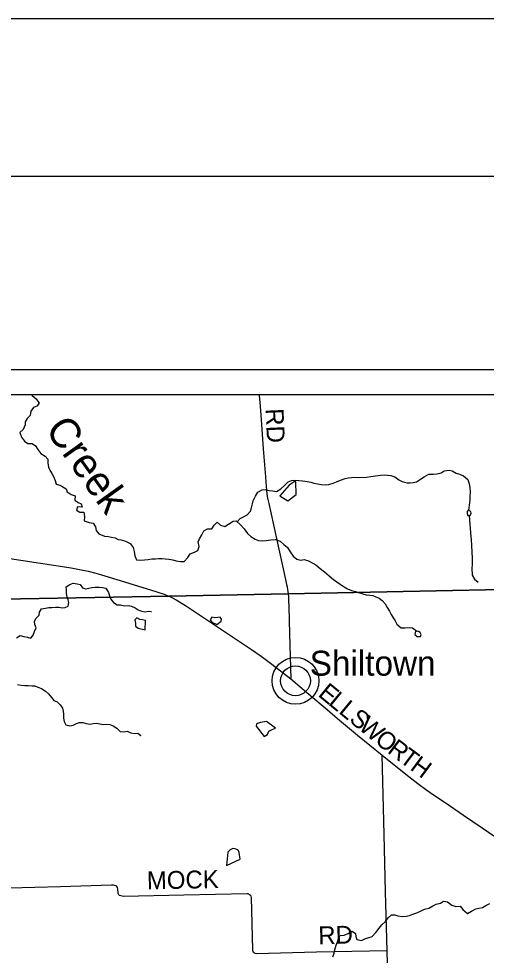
# Model space of a CAD drawing. Extents: x 0 to 34, y 0 to 22.
# Drawn here: x 5.224 to 6.707, y 19.028 to 22 of the extents above; entities that cross this region are included whole.
import ezdxf

# ---------------------------------------------------------------- set-up
doc = ezdxf.new("R2010")
doc.units = 0
for name, color, linetype in [('GM_X_Corporation', 7, 'Continuous'), ('GM_X_County_Road', 7, 'Continuous'), ('GM_X_County_Road_Text', 7, 'Continuous'), ('GM_X_Minor_Lake', 7, 'Continuous'), ('GM_X_Minor_River', 7, 'Continuous'), ('GM_X_Minor_River_Text', 7, 'Continuous'), ('GM_X_Township_Road', 7, 'Continuous'), ('GM_X_Unincorporated', 7, 'Continuous'), ('GM_X_Unincorporated_Location', 7, 'Continuous'), ('GM_X_Unincorporated_Text', 7, 'Continuous'), ('SH_Border', 7, 'Continuous'), ('SH_Cut_Line', 7, 'Continuous'), ('SH_Data', 7, 'Continuous')]:
    doc.layers.add(name, color=color, linetype=linetype)

msp = doc.modelspace()

# ---------------------------------------------------------------- linework, layer by layer
at = {"layer": 'GM_X_Corporation'}
msp.add_lwpolyline([(7.2136, 20.8069), (2.9895, 20.8069), (2.9895, 20.1176), (3.1549, 20.1187), (4.9925, 20.1548), (5.7004, 20.168), (6.0786, 20.1754), (7.2254, 20.198), (7.2157, 20.6753), (7.2146, 20.7526)], close=True, dxfattribs=at)
msp.add_lwpolyline([(7.2872, 17.1772), (7.283, 17.3071), (7.2799, 17.4174), (7.2764, 17.5202), (7.2751, 17.5764), (7.2467, 19.0557), (7.2468, 19.0896), (7.2426, 19.2998), (7.2392, 19.4543), (7.237, 19.6097), (7.2344, 19.7492), (7.2317, 19.8848), (7.2291, 20.0061), (7.2266, 20.122), (7.2254, 20.198), (6.0786, 20.1754), (5.7004, 20.168), (4.9925, 20.1548), (3.1549, 20.1187), (2.9895, 20.1176), (2.9895, 14.989)], dxfattribs=at)
at = {"layer": 'GM_X_County_Road'}
for points in [[(5.9866, 20.8069), (5.9868, 20.8036), (5.9886, 20.7837), (5.9932, 20.7287), (5.9994, 20.6355), (6.006, 20.5464), (6.0073, 20.5298), (6.0087, 20.5163), (6.0099, 20.504), (6.0111, 20.4923), (6.0133, 20.4791), (6.0171, 20.4614), (6.0397, 20.3598), (6.0698, 20.2206), (6.0733, 20.2043), (6.0747, 20.1975), (6.0763, 20.1891), (6.0777, 20.1824), (6.0788, 20.1749)], [(4.9883, 20.3188), (5.1818, 20.289), (5.3898, 20.2573), (5.4168, 20.2524), (5.4434, 20.2468), (5.4679, 20.2408), (5.4969, 20.2325), (5.5346, 20.2207), (5.6555, 20.1834), (5.6709, 20.1787)], [(5.6709, 20.1787), (5.6747, 20.1776), (5.6849, 20.1741), (5.694, 20.1704), (5.7006, 20.1675), (5.7093, 20.1632), (5.723, 20.156), (5.734, 20.1499), (5.7554, 20.1363), (5.838, 20.0814), (5.9084, 20.0341), (5.9617, 19.9985), (5.9928, 19.9771), (6.0264, 19.9525), (6.0866, 19.9058)], [(6.0788, 20.1749), (6.0793, 20.166), (6.0796, 20.1527), (6.0802, 20.1354), (6.0823, 20.0486), (6.0866, 19.9058)], [(6.0866, 19.9058), (6.1443, 19.8572), (6.2021, 19.8083), (6.2352, 19.7801), (6.2988, 19.727), (6.3765, 19.6635), (6.4512, 19.6033), (6.4897, 19.573), (6.5179, 19.5524), (6.5426, 19.5352), (6.5762, 19.5126), (6.6344, 19.4729), (6.6938, 19.4327), (6.7714, 19.3798), (6.8099, 19.3535), (6.8403, 19.3326), (6.8836, 19.3029), (6.9403, 19.2642), (6.994, 19.2279), (7.0243, 19.2074), (7.0735, 19.1741), (7.1379, 19.1298), (7.2009, 19.0868), (7.2469, 19.0552)], [(6.3926, 19.0426), (6.1683, 19.0378), (5.9778, 19.0332), (5.974, 19.0341), (5.9714, 19.0353), (5.9688, 19.0373), (5.9671, 19.0398), (5.9664, 19.0424), (5.9662, 19.0454), (5.9618, 19.2116), (5.9607, 19.2154), (5.9586, 19.2181), (5.9561, 19.2203), (5.9535, 19.2219), (5.951, 19.223), (5.9482, 19.2235), (5.7474, 19.219), (5.5563, 19.2152), (5.5514, 19.2155), (5.547, 19.2166), (5.5436, 19.2183), (5.5413, 19.2204), (5.54, 19.2227), (5.5391, 19.2256), (5.5375, 19.2393), (5.5367, 19.2434), (5.5343, 19.2464), (5.5312, 19.2484), (5.5279, 19.2497), (5.524, 19.2505), (5.5184, 19.2507), (5.356, 19.2459), (5.1937, 19.2412)]]:
    msp.add_lwpolyline(points, dxfattribs=at)
at = {"layer": 'GM_X_Minor_Lake'}
for points in [[(6.1037, 20.4902), (6.1027, 20.5305), (6.097, 20.5304), (6.0812, 20.5196), (6.0524, 20.4865), (6.0769, 20.4705)], [(6.0769, 20.4705), (6.1037, 20.4902)], [(6.649, 20.4411), (6.6461, 20.4364), (6.6463, 20.4296), (6.6487, 20.4236), (6.6559, 20.4238), (6.6584, 20.4307), (6.6575, 20.4352), (6.6556, 20.4374)], [(6.6556, 20.4374), (6.6541, 20.4394), (6.6514, 20.4408), (6.6498, 20.4413), (6.649, 20.4411)], [(5.6257, 20.0908), (5.6162, 20.0929), (5.6078, 20.094), (5.5979, 20.0988), (5.5923, 20.0926), (5.5935, 20.082), (5.5944, 20.0721), (5.6021, 20.0661), (5.6242, 20.0611)], [(5.6242, 20.0611), (5.6257, 20.0908)], [(5.8661, 20.088), (5.8668, 20.0945), (5.8629, 20.1009), (5.8553, 20.1001), (5.8462, 20.0992), (5.8363, 20.101), (5.8311, 20.0929), (5.8357, 20.0857), (5.8518, 20.0776)], [(5.8518, 20.0776), (5.8661, 20.088)], [(6.4827, 20.0566), (6.4807, 20.0463), (6.4881, 20.04), (6.498, 20.0399), (6.5001, 20.0464), (6.4973, 20.0528), (6.4919, 20.0557), (6.49, 20.0561)], [(6.49, 20.0561), (6.4827, 20.0566)], [(6.0092, 19.77), (5.9902, 19.7671), (5.9812, 19.7639), (5.9778, 19.7612), (5.9771, 19.7551), (6.0026, 19.7228), (6.0128, 19.729), (6.0165, 19.7397), (6.0274, 19.7447), (6.038, 19.749)], [(6.038, 19.749), (6.0092, 19.77)], [(5.9258, 19.3336), (5.9228, 19.3548), (5.9193, 19.362), (5.9155, 19.3642), (5.9101, 19.3661), (5.9032, 19.3668), (5.8942, 19.3628), (5.887, 19.3555), (5.8831, 19.3133)], [(5.8831, 19.3133), (5.9258, 19.3336)]]:
    msp.add_lwpolyline(points, dxfattribs=at)
at = {"layer": 'GM_X_Minor_River'}
for points in [[(5.2639, 20.8069), (5.2658, 20.8049), (5.279, 20.7938), (5.2888, 20.7803), (5.2811, 20.7707), (5.2709, 20.7662), (5.2625, 20.7543), (5.2597, 20.7413), (5.25, 20.7319), (5.2442, 20.7208), (5.2437, 20.7109), (5.2375, 20.697), (5.2275, 20.6869), (5.2328, 20.6726), (5.2415, 20.6595), (5.2523, 20.6525), (5.266, 20.6525), (5.2764, 20.6447), (5.2843, 20.6331), (5.2941, 20.62), (5.3076, 20.6124), (5.3155, 20.6023), (5.3154, 20.5905), (5.3183, 20.5776), (5.3227, 20.5679), (5.3287, 20.5574), (5.3339, 20.5472), (5.3387, 20.5348)], [(5.9164, 20.4037), (5.9266, 20.4147), (5.9363, 20.4199), (5.9488, 20.4255), (5.9584, 20.4379), (5.9619, 20.4478), (5.965, 20.4608), (5.9675, 20.4708), (5.9751, 20.485), (5.9824, 20.4981), (5.9956, 20.5057), (6.0054, 20.5059), (6.0184, 20.5035), (6.0291, 20.5015), (6.0417, 20.5003), (6.0556, 20.5082), (6.0664, 20.5187), (6.0787, 20.5304), (6.0892, 20.5352), (6.0991, 20.5355), (6.112, 20.535), (6.1238, 20.5337), (6.1391, 20.5318), (6.1498, 20.529), (6.1602, 20.5262), (6.1712, 20.5238), (6.1838, 20.5218), (6.1953, 20.5206), (6.2071, 20.5216), (6.2214, 20.5265), (6.2316, 20.5309), (6.244, 20.5362), (6.2587, 20.5415), (6.2689, 20.5436), (6.2792, 20.5442), (6.2913, 20.5449), (6.3016, 20.5447), (6.3271, 20.5453), (6.3411, 20.5472), (6.3555, 20.5494), (6.3714, 20.5517), (6.3832, 20.5524), (6.3939, 20.5518), (6.4038, 20.5506), (6.4164, 20.5459), (6.4292, 20.5371), (6.4396, 20.5316), (6.4545, 20.527), (6.4652, 20.5269), (6.4751, 20.5283), (6.486, 20.5308), (6.498, 20.5394), (6.5096, 20.5469), (6.5243, 20.5545), (6.5391, 20.5552), (6.5497, 20.5559), (6.5633, 20.5592), (6.5735, 20.5655), (6.5886, 20.5678), (6.5982, 20.565), (6.6113, 20.5584), (6.6216, 20.5549), (6.6347, 20.5495), (6.6479, 20.5384), (6.6524, 20.5244), (6.6546, 20.5127), (6.6557, 20.4975), (6.6549, 20.4846), (6.6543, 20.475), (6.6531, 20.4644), (6.6508, 20.441)], [(5.3387, 20.5348), (5.342, 20.5234), (5.3539, 20.5195), (5.3636, 20.5144), (5.374, 20.5086), (5.3769, 20.4988), (5.39, 20.4907), (5.403, 20.4861), (5.4018, 20.4728), (5.4123, 20.465), (5.4219, 20.4603), (5.4244, 20.4505), (5.4103, 20.4517), (5.4067, 20.4406), (5.4175, 20.4344), (5.4305, 20.4339), (5.4323, 20.4195), (5.4311, 20.4069), (5.4469, 20.4012), (5.4602, 20.3992), (5.4669, 20.388), (5.4695, 20.3763), (5.4777, 20.3654), (5.4962, 20.3586), (5.5088, 20.3567), (5.5183, 20.3554), (5.5294, 20.3533), (5.539, 20.3471), (5.5489, 20.3462), (5.5627, 20.3419), (5.5773, 20.3354), (5.5871, 20.3227), (5.5897, 20.3095), (5.5923, 20.2959), (5.5972, 20.2834), (5.6109, 20.2815), (5.6231, 20.2829), (5.6337, 20.2843), (5.6454, 20.2861), (5.6572, 20.2867), (5.6671, 20.2874), (5.6774, 20.2872), (5.688, 20.2863), (5.6999, 20.2855), (5.7128, 20.2831), (5.7228, 20.2799), (5.7373, 20.2776), (5.7484, 20.2775), (5.7602, 20.2903), (5.7679, 20.3019), (5.7811, 20.3075), (5.7916, 20.3131), (5.7959, 20.325), (5.7933, 20.3401), (5.7969, 20.3497), (5.8042, 20.3628), (5.8103, 20.3755), (5.8228, 20.3811), (5.8357, 20.3814), (5.8434, 20.3934), (5.8531, 20.4027), (5.8636, 20.3927), (5.877, 20.3892), (5.889, 20.3967), (5.904, 20.4054), (5.9134, 20.4064), (5.9274, 20.3938), (5.9391, 20.3812), (5.9494, 20.3666), (5.9595, 20.3573), (5.9738, 20.3489), (5.9841, 20.3446), (5.9971, 20.3434), (6.0089, 20.344), (6.0229, 20.3462), (6.0377, 20.3473), (6.0527, 20.3424), (6.0647, 20.3316), (6.076, 20.322), (6.085, 20.3085), (6.0937, 20.2947), (6.1057, 20.2847), (6.1184, 20.2816), (6.129, 20.2837), (6.1424, 20.2795), (6.1562, 20.2722), (6.1659, 20.2671), (6.1794, 20.256), (6.1938, 20.2453), (6.2082, 20.2323), (6.2217, 20.2209), (6.2326, 20.2128), (6.2434, 20.2058), (6.2562, 20.197), (6.2662, 20.1907), (6.2789, 20.1853), (6.2915, 20.1822), (6.3014, 20.1798), (6.3149, 20.1751), (6.3263, 20.1724), (6.337, 20.1711)], [(6.6527, 20.4237), (6.6543, 20.3948), (6.6557, 20.3823), (6.6572, 20.3702), (6.6583, 20.3565), (6.6592, 20.3467), (6.6604, 20.33), (6.6609, 20.3079), (6.6621, 20.2893), (6.6623, 20.2798), (6.6619, 20.2669), (6.6614, 20.2566), (6.6619, 20.2346), (6.6694, 20.2222), (6.6814, 20.2126)], [(5.2169, 20.0352), (5.2279, 20.0433), (5.2401, 20.0399), (5.2511, 20.0381), (5.2622, 20.0348), (5.2689, 20.0444), (5.2738, 20.0554), (5.279, 20.0672), (5.2751, 20.0775), (5.2731, 20.087), (5.278, 20.0969), (5.2881, 20.1072), (5.2896, 20.1167), (5.2959, 20.1278), (5.3081, 20.1298), (5.3191, 20.1314), (5.329, 20.1319), (5.3404, 20.1324), (5.3503, 20.1324), (5.361, 20.1306), (5.3704, 20.1322), (5.3803, 20.1361), (5.3825, 20.1472), (5.3805, 20.1566), (5.3774, 20.1661), (5.3754, 20.1767), (5.3753, 20.1878), (5.374, 20.1976), (5.3862, 20.2046), (5.3964, 20.2088), (5.4086, 20.2067), (5.4189, 20.2045)], [(5.4189, 20.2045), (5.4254, 20.1939), (5.4357, 20.1909), (5.4456, 20.1929), (5.4551, 20.1956), (5.4661, 20.1961), (5.4786, 20.1962), (5.4897, 20.1952), (5.4996, 20.1933), (5.5085, 20.1797), (5.512, 20.1687), (5.5155, 20.1581), (5.5247, 20.1472), (5.5362, 20.1408), (5.5469, 20.1401), (5.5587, 20.1376), (5.5708, 20.138), (5.5815, 20.1362), (5.5926, 20.1306), (5.6025, 20.1246), (5.6128, 20.1205), (5.6243, 20.118), (5.6345, 20.1199), (5.644, 20.1196), (5.6448, 20.1193)], [(6.337, 20.1711), (6.3469, 20.1694), (6.3569, 20.1659), (6.3669, 20.1612), (6.3766, 20.1542), (6.386, 20.1437), (6.3923, 20.1317), (6.3995, 20.1197), (6.4047, 20.1096), (6.411, 20.0991), (6.4173, 20.089), (6.4236, 20.0792), (6.4368, 20.067), (6.4494, 20.0669), (6.4631, 20.0687), (6.4726, 20.0678), (6.4866, 20.0563)], [(5.2201, 19.887), (5.2308, 19.8855), (5.2434, 19.8841), (5.2536, 19.8846), (5.2647, 19.8832), (5.2742, 19.8829), (5.2841, 19.8791), (5.2963, 19.8747), (5.3082, 19.8668), (5.3185, 19.8578), (5.3274, 19.8464), (5.3351, 19.8366), (5.345, 19.8325), (5.355, 19.8235), (5.3623, 19.8125), (5.3647, 19.8026), (5.3659, 19.7931), (5.366, 19.781), (5.3672, 19.7704), (5.3726, 19.7598), (5.3852, 19.7564), (5.3962, 19.758), (5.4065, 19.7642), (5.4159, 19.7669), (5.427, 19.7674), (5.438, 19.7633), (5.4498, 19.7619), (5.4597, 19.7639), (5.47, 19.7643), (5.4814, 19.7622), (5.4917, 19.7603), (5.5019, 19.7619), (5.513, 19.7609), (5.5233, 19.7564), (5.5348, 19.7493), (5.5459, 19.7387), (5.5569, 19.7377), (5.568, 19.7393), (5.5794, 19.7341), (5.5908, 19.7315), (5.6011, 19.7331), (5.6107, 19.7252), (5.6099, 19.7248)], [(6.2202, 19.0229), (6.2245, 19.0348), (6.2265, 19.0459), (6.2307, 19.0601), (6.2347, 19.0712), (6.2382, 19.0815), (6.2437, 19.0912), (6.2555, 19.0926), (6.2691, 19.0971), (6.281, 19.105), (6.2922, 19.0976), (6.2925, 19.0877), (6.2965, 19.0779), (6.311, 19.0756), (6.3216, 19.0808), (6.3314, 19.0841), (6.3446, 19.0878), (6.3569, 19.1003), (6.3668, 19.1142), (6.3757, 19.1247), (6.3872, 19.1359), (6.3953, 19.1468), (6.4057, 19.1565), (6.4168, 19.1564), (6.4267, 19.1536), (6.4416, 19.1517), (6.453, 19.1523), (6.4629, 19.1544), (6.4738, 19.1585), (6.487, 19.1626), (6.5006, 19.169), (6.5111, 19.1742), (6.5247, 19.1779), (6.5378, 19.1851), (6.5476, 19.1906), (6.5612, 19.1932), (6.5713, 19.1999), (6.5843, 19.198), (6.5971, 19.1868), (6.6105, 19.183), (6.6235, 19.1837), (6.6328, 19.1732), (6.6468, 19.161), (6.6603, 19.1678), (6.6739, 19.1753), (6.6837, 19.1775), (6.695, 19.1804), (6.7052, 19.1859), (6.7183, 19.1931)]]:
    msp.add_lwpolyline(points, dxfattribs=at)
at = {"layer": 'GM_X_Township_Road'}
msp.add_lwpolyline([(6.408, 18.4195), (6.4068, 18.4524), (6.4043, 18.5569), (6.3989, 18.7778), (6.3954, 18.9178), (6.3926, 19.0426), (6.3876, 19.2294), (6.383, 19.4112), (6.3765, 19.6635)], dxfattribs=at)
at = {"layer": 'GM_X_Unincorporated'}
for radius in [0.0744, 0.0472]:
    msp.add_circle((6.1015, 19.8992), radius, dxfattribs=at)
at = {"layer": 'GM_X_Unincorporated_Location'}
msp.add_line((6.1015, 19.8992), (6.1015, 19.8992), dxfattribs=at)
at = {"layer": 'SH_Border'}
msp.add_lwpolyline([(1.5, 21.5), (33.5, 21.5), (33.5, 0.5), (1.5, 0.5)], close=True, dxfattribs=at)
at = {"layer": 'SH_Cut_Line'}
msp.add_lwpolyline([(0, 0), (34, 0), (34, 22), (0, 22)], close=True, dxfattribs=at)
at = {"layer": 'SH_Data'}
msp.add_line((2.8945, 20.8873), (9.8945, 20.8873), dxfattribs=at)

# ---------------------------------------------------------------- texts
at = {"layer": 'GM_X_County_Road_Text'}
for s, height, rotation, p in [('RD', 0.05682, 272.4668, (6.0067, 20.7625)), ('E', 0.0568, 320.5758, (6.1702, 19.8529)), ('L', 0.0568, 320.5759, (6.203, 19.8259)), ('L', 0.0568, 320.5788, (6.2359, 19.7989)), ('S', 0.0568, 320.5795, (6.2687, 19.772)), ('W', 0.0568, 320.6039, (6.2983, 19.7476)), ('O', 0.0568, 321.5282, (6.35, 19.7052)), ('R', 0.0568, 322.9628, (6.3903, 19.6731)), ('T', 0.0568, 323.3792, (6.428, 19.6448)), ('H', 0.0568, 323.3756, (6.4621, 19.6194)), ('MOCK', 0.05682, 1.146, (5.6306, 19.2372)), ('RD', 0.05682, 1.4826, (6.1746, 19.063))]:
    msp.add_text(s, height=height, rotation=rotation, dxfattribs=at).set_placement(p)
at = {"layer": 'GM_X_Minor_River_Text'}
msp.add_text('Creek', height=0.09473, rotation=305.5513, dxfattribs=at).set_placement((5.3052, 20.6964))
at = {"layer": 'GM_X_Unincorporated_Text'}
msp.add_text('Shiltown', height=0.07898, rotation=0, dxfattribs=at).set_placement((6.1468, 19.9156))

doc.saveas('drawing.dxf')
